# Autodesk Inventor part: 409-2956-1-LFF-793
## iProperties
Shininess: 64.0
Angle Display Precision: 2
Document Length Units: 11272
Document Angle Units: 11279
Document Time Units: 11290
Document Mass Units: 11286
Document Length Units Precision: 3
Document Angle Units Precision: 2
Compacted: True
Created: 2002-04
Part Number: 409-2956-1-LFF-793
Description: 2" PIPE MOUNT ANGLE
Document SubType Name: Modeling
Designer: S. Boerckel
Mass: 2540.04 g
Surface Area: 1040.68 cm^2
Volume: 316.319 cm^3
Density: 8.03 g/cm^3
Cost Center: 3 x 3 x 1/4 ANGLE
Material: STAINLESS STEEL, 304
Engineer: S. Boerckel
Density: 0.0
Volumn: 0.0
Area: 0.0
PropertySet Name: Model Information
Control State: 0
Master: False
Checked Out: False
length: 13.500 in
SMR: =<COST CENTER> - <MATERIAL>
Author: S. Boerckel
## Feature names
1. Extrusion1
2. Hole1
